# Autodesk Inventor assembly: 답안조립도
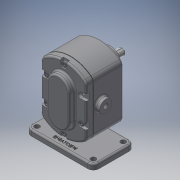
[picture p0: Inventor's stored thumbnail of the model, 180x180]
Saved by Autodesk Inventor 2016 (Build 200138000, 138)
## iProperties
Created: 2019-03
Part Number: 답안조립도
Material: 일반
Document SubType Name: Assembly
Designer: USER
Author: USER
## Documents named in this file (11)
- C:\Users\USER\Desktop\490307V1020\답안조립도.iam
- C:\Users\USER\Desktop\490307V1020\부품.ipt
- C:\Users\USER\Desktop\490307V1020\서브축.ipt
- C:\Users\USER\Desktop\490307V1020\스퍼기어.ipt
- C:\Users\USER\Desktop\490307V1020\오일 실 16 28 7.ipt
- C:\Users\USER\Desktop\490307V1020\커버.ipt
- C:\Users\USER\Desktop\490307V1020\키 6 x 6 x 18.ipt
- C:\Users\USER\Desktop\490307V1020\개스킷.ipt
- C:\Users\USER\Desktop\490307V1020\메인축.ipt
- C:\Users\USER\Desktop\490307V1020\베어링부시.ipt
- C:\Users\USER\Desktop\490307V1020\볼트 M5.ipt
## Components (1 placed, 1 different names)
1. 개스킷:1
